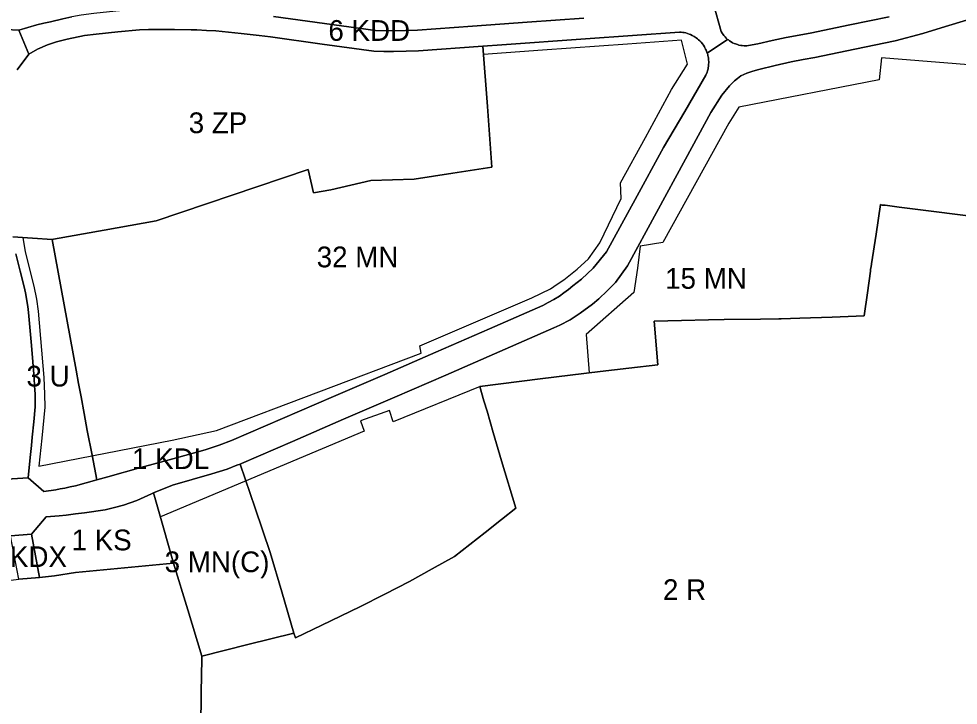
# Model space of a CAD drawing. Extents: x -294445 to -292055, y 21869 to 23693.
# Drawn here: x -292845.3 to -292392.4, y 22598.3 to 22929.3 of the extents above; entities that cross this region are included whole.
import ezdxf

# ---------------------------------------------------------------- set-up
doc = ezdxf.new("R2010")
doc.units = 0
for name, color, linetype in [('linie_rozgraniczajace', 7, 'Continuous'), ('linie_zabudowy_nieprzekraczalne', 7, 'Continuous'), ('oznaczenia_przeznaczen', 7, 'Continuous')]:
    doc.layers.add(name, color=color, linetype=linetype)

msp = doc.modelspace()

# ---------------------------------------------------------------- linework, layer by layer
at = {"layer": 'linie_rozgraniczajace'}
for points in [[(-292877.28, 22963.509), (-292771.589, 22956.531), (-292773.918, 22939.989), (-292779.321, 22934.119), (-292787.762, 22933.952), (-292798.439, 22932.873), (-292809.117, 22931.794), (-292815.239, 22931.067), (-292819.688, 22930.162), (-292824.138, 22929.257), (-292829.968, 22927.793), (-292833.288, 22927.089), (-292836.609, 22926.385), (-292845.246, 22923.759), (-292851.578, 22924.027)], [(-292510.365, 22936.24), (-292506.657, 22923.115), (-292506.177, 22922.315), (-292505.782, 22921.742), (-292505.369, 22921.202), (-292504.762, 22920.503), (-292504.221, 22919.954), (-292503.55, 22919.353), (-292513.355, 22912.718), (-292513.507, 22913.17), (-292513.671, 22913.608), (-292513.917, 22914.198), (-292514.146, 22914.687), (-292514.47, 22915.312), (-292514.672, 22915.667), (-292515.232, 22916.545), (-292515.746, 22917.245), (-292516.34, 22917.957), (-292517.003, 22918.655), (-292517.549, 22919.166), (-292518.135, 22919.659), (-292518.688, 22920.079), (-292519.617, 22920.697), (-292520.661, 22921.278), (-292521.403, 22921.625), (-292522.129, 22921.918), (-292522.829, 22922.158), (-292523.759, 22922.417), (-292524.518, 22922.581), (-292525.09, 22922.676), (-292525.998, 22922.78), (-292526.722, 22922.821), (-292549.423, 22921.234), (-292572.124, 22919.647), (-292612.336, 22916.752), (-292621.574, 22916.087), (-292652.549, 22913.857), (-292658.559, 22913.677), (-292664.57, 22913.497), (-292669.314, 22913.568), (-292674.059, 22913.639), (-292698.973, 22917.065), (-292723.887, 22920.492), (-292729.473, 22921.204), (-292733.8, 22921.702), (-292738.126, 22922.2), (-292744.174, 22922.79), (-292750.222, 22923.379), (-292754.873, 22923.652), (-292759.525, 22923.924), (-292762.113, 22923.937), (-292770.193, 22924.022), (-292778.272, 22924.107), (-292782.724, 22924.034), (-292787.175, 22923.96), (-292797.6, 22922.907), (-292808.024, 22921.853), (-292813.65, 22921.185), (-292821.922, 22919.503), (-292827.092, 22918.204), (-292831.455, 22916.678), (-292836.35, 22914.6), (-292840.509, 22912.145), (-292845.246, 22923.759), (-292836.609, 22926.385), (-292833.288, 22927.089), (-292829.968, 22927.793), (-292824.138, 22929.257), (-292819.688, 22930.162)], [(-292425.606, 22930.273), (-292444.67, 22926.318), (-292463.734, 22922.363), (-292475.314, 22920.318), (-292482.16, 22918.739), (-292489.006, 22917.159), (-292493.554, 22916.346), (-292494.347, 22916.281), (-292495.008, 22916.264), (-292495.598, 22916.276), (-292496.502, 22916.346), (-292497.176, 22916.438), (-292498.071, 22916.616), (-292498.744, 22916.793), (-292499.705, 22917.113), (-292500.427, 22917.409), (-292501.138, 22917.75), (-292501.827, 22918.133), (-292502.588, 22918.622), (-292503.185, 22919.059), (-292503.55, 22919.353), (-292504.221, 22919.954), (-292504.762, 22920.503), (-292505.369, 22921.202), (-292505.782, 22921.742), (-292506.177, 22922.315), (-292506.657, 22923.115), (-292510.365, 22936.24)], [(-292388.39, 22928.526), (-292398.467, 22925.492), (-292409.406, 22922.161), (-292422.845, 22918.591), (-292442.158, 22914.584), (-292461.472, 22910.576), (-292467.174, 22909.57), (-292472.876, 22908.563), (-292480.676, 22906.703), (-292488.476, 22904.842), (-292491.41, 22903.937), (-292494.345, 22903.031), (-292495.784, 22902.363), (-292497.223, 22901.695), (-292498.729, 22900.524), (-292500.235, 22899.353), (-292501.442, 22898.147), (-292502.649, 22896.941), (-292506.318, 22892.426), (-292511.609, 22884.079), (-292517.755, 22872.806), (-292523.901, 22861.532), (-292537.897, 22835.859), (-292551.893, 22810.186), (-292554.78, 22806.143), (-292557.667, 22802.1), (-292561.65, 22798.151), (-292565.633, 22794.202), (-292568.767, 22791.723), (-292574.61, 22787.286), (-292579.405, 22784.082), (-292584.435, 22781.511), (-292587.378, 22780.188), (-292613.385, 22768.847), (-292639.392, 22757.506), (-292664.072, 22746.822), (-292688.751, 22736.138), (-292713.363, 22725.483), (-292737.975, 22714.828), (-292738.581, 22714.588), (-292740.146, 22713.97), (-292744.81, 22712.128), (-292752.205, 22709.893), (-292761.697, 22707.124), (-292771.19, 22704.354), (-292780.356, 22700.664), (-292781.357, 22700.246), (-292788.373, 22697.064), (-292794.741, 22694.706), (-292799.198, 22693.614), (-292803.656, 22692.522), (-292813.582, 22691.094)], [(-292738.581, 22714.588), (-292737.975, 22714.828), (-292713.363, 22725.483), (-292688.751, 22736.138), (-292664.072, 22746.822), (-292639.392, 22757.506), (-292613.385, 22768.847), (-292587.378, 22780.188), (-292584.435, 22781.511), (-292579.405, 22784.082), (-292574.61, 22787.286), (-292568.767, 22791.723), (-292565.633, 22794.202), (-292561.65, 22798.151), (-292557.667, 22802.1), (-292554.78, 22806.143), (-292551.893, 22810.186), (-292537.897, 22835.859), (-292523.901, 22861.532), (-292517.755, 22872.806), (-292511.609, 22884.079), (-292506.318, 22892.426), (-292502.649, 22896.941), (-292501.442, 22898.147), (-292500.235, 22899.353), (-292498.729, 22900.524), (-292497.223, 22901.695), (-292495.784, 22902.363), (-292494.345, 22903.031), (-292491.41, 22903.937), (-292488.476, 22904.842), (-292480.676, 22906.703), (-292472.876, 22908.563), (-292467.174, 22909.57), (-292461.472, 22910.576), (-292442.158, 22914.584), (-292422.845, 22918.591), (-292409.406, 22922.161), (-292398.467, 22925.492), (-292388.39, 22928.526)], [(-292572.832, 22929.622), (-292600.173, 22927.654), (-292626.616, 22925.75), (-292653.058, 22923.847), (-292658.851, 22923.673), (-292664.645, 22923.499), (-292673.3, 22923.629), (-292697.936, 22927.017), (-292722.573, 22930.405)], [(-292722.573, 22930.405), (-292697.936, 22927.017), (-292673.3, 22923.629), (-292664.645, 22923.499), (-292658.851, 22923.673), (-292653.058, 22923.847), (-292626.616, 22925.75), (-292600.173, 22927.654), (-292572.832, 22929.622)], [(-292587.34, 22793.884), (-292584.621, 22795.551), (-292582.541, 22797.123), (-292580.337, 22798.788), (-292578.205, 22800.464), (-292573.972, 22803.786), (-292568.358, 22808.972), (-292561.898, 22816.904), (-292548.168, 22842.09), (-292534.437, 22867.276), (-292524.23, 22884.641), (-292514.023, 22902.007), (-292513.465, 22903.561), (-292513.269, 22904.171), (-292513.014, 22905.156), (-292512.9, 22905.72), (-292512.816, 22906.24), (-292512.746, 22906.806), (-292512.699, 22907.357), (-292512.671, 22908.015), (-292512.674, 22908.725), (-292512.708, 22909.371), (-292512.762, 22909.949), (-292512.829, 22910.461), (-292512.911, 22910.948), (-292513.024, 22911.5), (-292513.138, 22911.969), (-292513.355, 22912.718), (-292503.55, 22919.353), (-292503.185, 22919.059), (-292502.588, 22918.622), (-292501.827, 22918.133), (-292501.138, 22917.75), (-292500.427, 22917.409), (-292499.705, 22917.113), (-292498.744, 22916.793), (-292498.071, 22916.616), (-292497.176, 22916.438), (-292496.502, 22916.346), (-292495.598, 22916.276), (-292495.008, 22916.264), (-292494.347, 22916.281), (-292493.554, 22916.346), (-292489.006, 22917.159), (-292482.16, 22918.739), (-292475.314, 22920.318), (-292463.734, 22922.363), (-292444.67, 22926.318), (-292425.606, 22930.273)], [(-292851.578, 22924.027), (-292845.246, 22923.759), (-292840.509, 22912.145), (-292846.02, 22904.62)], [(-292846.02, 22904.62), (-292840.509, 22912.145), (-292836.35, 22914.6), (-292831.455, 22916.678), (-292827.092, 22918.204), (-292821.922, 22919.503), (-292813.65, 22921.185), (-292808.024, 22921.853), (-292797.6, 22922.907), (-292787.175, 22923.96), (-292782.724, 22924.034), (-292778.272, 22924.107), (-292770.193, 22924.022), (-292762.113, 22923.937), (-292759.525, 22923.924), (-292754.873, 22923.652), (-292750.222, 22923.379), (-292744.174, 22922.79), (-292738.126, 22922.2), (-292733.8, 22921.702), (-292729.473, 22921.204), (-292723.887, 22920.492), (-292698.973, 22917.065), (-292674.059, 22913.639), (-292669.314, 22913.568), (-292664.57, 22913.497), (-292658.559, 22913.677), (-292652.549, 22913.857), (-292621.574, 22916.087), (-292619.377, 22886.924), (-292617.18, 22857.76), (-292635.965, 22854.855), (-292654.75, 22851.95), (-292665.14, 22851.585), (-292675.53, 22851.22), (-292685.225, 22849.04), (-292694.92, 22846.86), (-292703.282, 22845.367), (-292704.536, 22850.949), (-292705.79, 22856.53), (-292742.393, 22844.19), (-292778.996, 22831.851), (-292804.117, 22827.366), (-292828.532, 22823.007), (-292829.22, 22822.88), (-292838.706, 22823.542), (-292848.193, 22824.203)], [(-292757.59, 22587.46), (-292757.32, 22604.665), (-292757.071, 22620.541), (-292757.05, 22621.87), (-292734.86, 22627.49), (-292712.67, 22633.11), (-292711.94, 22630.84), (-292699.137, 22636.921), (-292680.86, 22645.74), (-292668.895, 22651.88), (-292656.93, 22658.02), (-292646.05, 22663.973), (-292635.16, 22670.02), (-292620.46, 22681.55), (-292612.495, 22687.86), (-292605.71, 22693.23), (-292612.585, 22716.145), (-292616.64, 22729.78), (-292618.1, 22734.895), (-292619.56, 22740.01), (-292621.027, 22745.09), (-292623.03, 22752.03), (-292593.99, 22755.595), (-292564.95, 22759.16), (-292551.115, 22760.8), (-292537.28, 22762.44), (-292538.97, 22783.51), (-292525.84, 22783.835), (-292512.71, 22784.16), (-292505.21, 22784.26), (-292487.72, 22784.495), (-292478.922, 22784.614), (-292477.73, 22784.63), (-292468.67, 22784.94), (-292453.18, 22785.475), (-292437.69, 22786.01), (-292436.17, 22797.115), (-292434.741, 22807.552), (-292434.603, 22808.544), (-292434.42, 22809.705), (-292434.19, 22811.19), (-292431.99, 22825.43), (-292429.79, 22839.67), (-292429.129, 22839.361), (-292427.66, 22839.39), (-292424.295, 22838.95), (-292420.93, 22838.51), (-292375.99, 22832.74)], [(-292375.99, 22832.74), (-292420.93, 22838.51), (-292424.295, 22838.95), (-292427.66, 22839.39), (-292429.129, 22839.361), (-292429.79, 22839.67), (-292431.99, 22825.43), (-292434.19, 22811.19), (-292434.42, 22809.705), (-292434.603, 22808.544), (-292434.741, 22807.552), (-292436.17, 22797.115), (-292437.69, 22786.01), (-292453.18, 22785.475), (-292468.67, 22784.94), (-292477.73, 22784.63), (-292478.922, 22784.614), (-292487.72, 22784.495), (-292505.21, 22784.26), (-292512.71, 22784.16), (-292525.84, 22783.835), (-292538.97, 22783.51), (-292537.28, 22762.44), (-292551.115, 22760.8), (-292564.95, 22759.16), (-292593.99, 22755.595), (-292623.03, 22752.03), (-292621.027, 22745.09), (-292619.56, 22740.01), (-292618.1, 22734.895), (-292616.64, 22729.78), (-292612.585, 22716.145), (-292605.71, 22693.23), (-292612.495, 22687.86), (-292620.46, 22681.55), (-292635.16, 22670.02), (-292646.05, 22663.973), (-292656.93, 22658.02), (-292668.895, 22651.88), (-292680.86, 22645.74), (-292699.137, 22636.921), (-292711.94, 22630.84)], [(-292848.193, 22824.203), (-292838.706, 22823.542), (-292829.22, 22822.88), (-292823.415, 22791.341), (-292817.609, 22759.802), (-292816.439, 22753.425), (-292815.268, 22747.048), (-292813.764, 22738.879), (-292812.26, 22730.71), (-292809.959, 22718.84), (-292807.658, 22706.971), (-292817.945, 22704.119), (-292820.548, 22703.568), (-292823.152, 22703.016), (-292825.317, 22702.569), (-292827.482, 22702.122), (-292833.281, 22701.294), (-292840.815, 22707.897), (-292839.794, 22717.727), (-292839.192, 22723.52), (-292838.773, 22727.558), (-292838.108, 22734.878), (-292837.443, 22742.197), (-292837.456, 22747.387), (-292837.462, 22748.387), (-292837.649, 22752.071), (-292837.841, 22755.929), (-292839.196, 22771.811), (-292840.552, 22787.693), (-292840.95, 22790.501), (-292841.349, 22793.31), (-292841.97, 22796.312), (-292842.591, 22799.315), (-292844.631, 22807.623), (-292846.67, 22815.93)], [(-292846.67, 22815.93), (-292844.631, 22807.623), (-292842.591, 22799.315), (-292841.97, 22796.312), (-292841.349, 22793.31), (-292840.95, 22790.501), (-292840.552, 22787.693), (-292839.196, 22771.811), (-292837.841, 22755.929), (-292837.649, 22752.071), (-292837.462, 22748.387), (-292837.456, 22747.387), (-292837.443, 22742.197), (-292838.108, 22734.878), (-292838.773, 22727.558), (-292839.192, 22723.52), (-292839.794, 22717.727), (-292840.815, 22707.897), (-292850.987, 22707.279)], [(-292850.987, 22707.279), (-292840.815, 22707.897), (-292833.281, 22701.294), (-292827.482, 22702.122), (-292825.317, 22702.569), (-292823.152, 22703.016), (-292820.548, 22703.568), (-292817.945, 22704.119), (-292807.658, 22706.971), (-292802.294, 22708.458), (-292786.49, 22712.84), (-292770.966, 22717.144), (-292755.442, 22721.448), (-292748.751, 22723.638), (-292742.668, 22725.872), (-292718.093, 22736.511), (-292693.519, 22747.15), (-292668.846, 22757.831), (-292644.174, 22768.512), (-292618.419, 22779.743), (-292592.664, 22790.974), (-292590.002, 22792.429), (-292587.34, 22793.884)], [(-292711.94, 22630.84), (-292712.67, 22633.11), (-292715.603, 22643.036), (-292718.536, 22652.962), (-292724.06, 22671.99), (-292731.321, 22693.289), (-292738.581, 22714.588)], [(-292813.582, 22691.094), (-292818.015, 22690.523), (-292822.448, 22689.952), (-292825.815, 22689.659), (-292832.045, 22689.14), (-292839.224, 22680.815), (-292849.226, 22679.902)], [(-292909.465, 22597.52), (-292911.95, 22608.56), (-292913.321, 22617.281), (-292914.693, 22626.001), (-292915.486, 22635.046), (-292916.28, 22644.09), (-292908.27, 22645.05), (-292900.26, 22646.01), (-292900.245, 22649.115), (-292900.23, 22652.22), (-292872.79, 22655.63), (-292845.35, 22659.04), (-292835.339, 22659.903), (-292828.13, 22660.71), (-292817.95, 22662.24), (-292794.31, 22664.53), (-292770.67, 22666.82), (-292763.86, 22644.345), (-292757.05, 22621.87), (-292757.071, 22620.541), (-292757.32, 22604.665), (-292757.59, 22587.46)]]:
    msp.add_lwpolyline(points, dxfattribs=at)
for points in [[(-292829.22, 22822.88), (-292828.532, 22823.007), (-292804.117, 22827.366), (-292778.996, 22831.851), (-292742.393, 22844.19), (-292705.79, 22856.53), (-292704.536, 22850.949), (-292703.282, 22845.367), (-292694.92, 22846.86), (-292685.225, 22849.04), (-292675.53, 22851.22), (-292665.14, 22851.585), (-292654.75, 22851.95), (-292635.965, 22854.855), (-292617.18, 22857.76), (-292619.377, 22886.924), (-292621.574, 22916.087), (-292612.336, 22916.752), (-292572.124, 22919.647), (-292549.423, 22921.234), (-292526.722, 22922.821), (-292525.998, 22922.78), (-292525.09, 22922.676), (-292524.518, 22922.581), (-292523.759, 22922.417), (-292522.829, 22922.158), (-292522.129, 22921.918), (-292521.403, 22921.625), (-292520.661, 22921.278), (-292519.617, 22920.697), (-292518.688, 22920.079), (-292518.135, 22919.659), (-292517.549, 22919.166), (-292517.003, 22918.655), (-292516.34, 22917.957), (-292515.746, 22917.245), (-292515.232, 22916.545), (-292514.672, 22915.667), (-292514.47, 22915.312), (-292514.146, 22914.687), (-292513.917, 22914.198), (-292513.671, 22913.608), (-292513.507, 22913.17), (-292513.355, 22912.718), (-292513.138, 22911.969), (-292513.024, 22911.5), (-292512.911, 22910.948), (-292512.829, 22910.461), (-292512.762, 22909.949), (-292512.708, 22909.371), (-292512.674, 22908.725), (-292512.671, 22908.015), (-292512.699, 22907.357), (-292512.746, 22906.806), (-292512.816, 22906.24), (-292512.9, 22905.72), (-292513.014, 22905.156), (-292513.269, 22904.171), (-292513.465, 22903.561), (-292514.023, 22902.007), (-292524.23, 22884.641), (-292534.437, 22867.276), (-292548.168, 22842.09), (-292561.898, 22816.904), (-292568.358, 22808.972), (-292573.972, 22803.786), (-292578.205, 22800.464), (-292580.337, 22798.788), (-292582.541, 22797.123), (-292584.621, 22795.551), (-292587.34, 22793.884), (-292590.002, 22792.429), (-292592.664, 22790.974), (-292618.419, 22779.743), (-292644.174, 22768.512), (-292668.846, 22757.831), (-292693.519, 22747.15), (-292718.093, 22736.511), (-292742.668, 22725.872), (-292748.751, 22723.638), (-292755.442, 22721.448), (-292770.966, 22717.144), (-292786.49, 22712.84), (-292802.294, 22708.458), (-292807.658, 22706.971), (-292809.959, 22718.84), (-292812.26, 22730.71), (-292813.764, 22738.879), (-292815.268, 22747.048), (-292816.439, 22753.425), (-292817.609, 22759.802), (-292823.415, 22791.341)], [(-292780.356, 22700.664), (-292771.19, 22704.354), (-292761.697, 22707.124), (-292752.205, 22709.893), (-292744.81, 22712.128), (-292740.146, 22713.97), (-292738.581, 22714.588), (-292731.321, 22693.289), (-292724.06, 22671.99), (-292718.536, 22652.962), (-292715.603, 22643.036), (-292712.67, 22633.11), (-292734.86, 22627.49), (-292757.05, 22621.87), (-292763.86, 22644.345), (-292770.67, 22666.82), (-292775.513, 22683.742)], [(-292839.224, 22680.815), (-292832.045, 22689.14), (-292825.815, 22689.659), (-292822.448, 22689.952), (-292818.015, 22690.523), (-292813.582, 22691.094), (-292803.656, 22692.522), (-292799.198, 22693.614), (-292794.741, 22694.706), (-292788.373, 22697.064), (-292781.357, 22700.246), (-292780.356, 22700.664), (-292775.513, 22683.742), (-292770.67, 22666.82), (-292794.31, 22664.53), (-292817.95, 22662.24), (-292828.13, 22660.71), (-292835.339, 22659.903), (-292837.282, 22670.359)], [(-292849.226, 22679.902), (-292839.224, 22680.815), (-292837.282, 22670.359), (-292835.339, 22659.903), (-292845.35, 22659.04)]]:
    msp.add_lwpolyline(points, close=True, dxfattribs=at)
at = {"layer": 'linie_zabudowy_nieprzekraczalne'}
for points in [[(-292525.745, 22918.88), (-292551.9, 22917.051), (-292592.793, 22914.149), (-292621.287, 22912.097)], [(-292565.14, 22821.162), (-292554.834, 22842.665), (-292555.219, 22850.156), (-292543.217, 22872.063), (-292530.578, 22895.245), (-292522.883, 22907.335), (-292525.745, 22918.88)], [(-292357.393, 22904.594), (-292429.359, 22910.43), (-292430.485, 22899.831), (-292430.485, 22899.831), (-292430.485, 22899.831), (-292430.485, 22899.831), (-292498.187, 22886.575), (-292498.187, 22886.575), (-292498.187, 22886.575), (-292498.187, 22886.575), (-292498.187, 22886.575), (-292502.986, 22879.004), (-292534.87, 22821.344), (-292545.64, 22819.59), (-292546.96, 22809.05), (-292548.795, 22797.227), (-292548.795, 22797.227), (-292571.814, 22776.968), (-292571.814, 22776.968), (-292570.232, 22758.512)], [(-292843.426, 22823.871), (-292842.144, 22816.902), (-292838.077, 22800.336), (-292836.788, 22794.104), (-292835.952, 22788.215), (-292833.223, 22756.24), (-292832.83, 22748.334), (-292832.815, 22741.993), (-292834.167, 22727.11), (-292835.582, 22713.481), (-292771.417, 22726.053)], [(-292651.246, 22768.085), (-292652.015, 22771.609), (-292597.902, 22794.694), (-292588.912, 22799.005), (-292585.691, 22801.257), (-292582.478, 22803.382), (-292576.041, 22808.481), (-292570.665, 22813.553), (-292565.14, 22821.162)], [(-292771.417, 22726.053), (-292749.94, 22730.73), (-292651.246, 22768.085)], [(-292622.839, 22752.008), (-292664.792, 22734.961), (-292666.568, 22740.43), (-292680.535, 22735.405), (-292678.708, 22730.457), (-292777.05, 22689.114)]]:
    msp.add_lwpolyline(points, dxfattribs=at)

# ---------------------------------------------------------------- texts
at = {"layer": 'oznaczenia_przeznaczen'}
for s, p in [('6 KDD', (-292696.026, 22918.629)), ('3 ZP', (-292763.373, 22874.114)), ('32 MN', (-292701.672, 22809.439)), ('15 MN', (-292533.679, 22799.087)), ('3 U', (-292841.589, 22751.967)), ('1 KDL', (-292790.701, 22712.144)), ('1 KS', (-292819.872, 22672.96)), ('13 KDX', (-292868.146, 22664.915)), ('3 MN(C)', (-292774.969, 22662.432)), ('2 R', (-292534.735, 22649.01))]:
    msp.add_text(s, height=10, dxfattribs=at).set_placement(p)

doc.saveas('drawing.dxf')
